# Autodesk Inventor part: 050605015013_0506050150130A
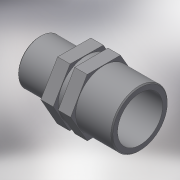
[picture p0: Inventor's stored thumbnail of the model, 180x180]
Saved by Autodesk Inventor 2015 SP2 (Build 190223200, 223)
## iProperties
Created: 2017-05
Part Number: 050605015013_0506050150130A
Material: Generic
Description: PLASSON REDUCING NIPPLE 1.1/2"-1.1/4"
Document SubType Name: Modeling
Designer: KIM
Density: 1 g/cm^3
Appearance: Default
Author: KIM
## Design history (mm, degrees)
derived "050605.ipt"
feature "Solid1::050605.ipt"
tag "TaggingFeature1"
body "Solid1"
other parameters: "d0" = 59, "d1" = 47.803, "d5" = 21, "d6" = 5.9, "d8" = 0.59, "d12" = 0, "d14" = 41.91, "d15" = 33.528, "d16" = 38.2424, "d17" = 21, "d18" = 2.95, "d21" = 0, "H_" = 59, "R_" = 47.803, "l_" = 21, "R_1" = 41.91, "l_1" = 21
